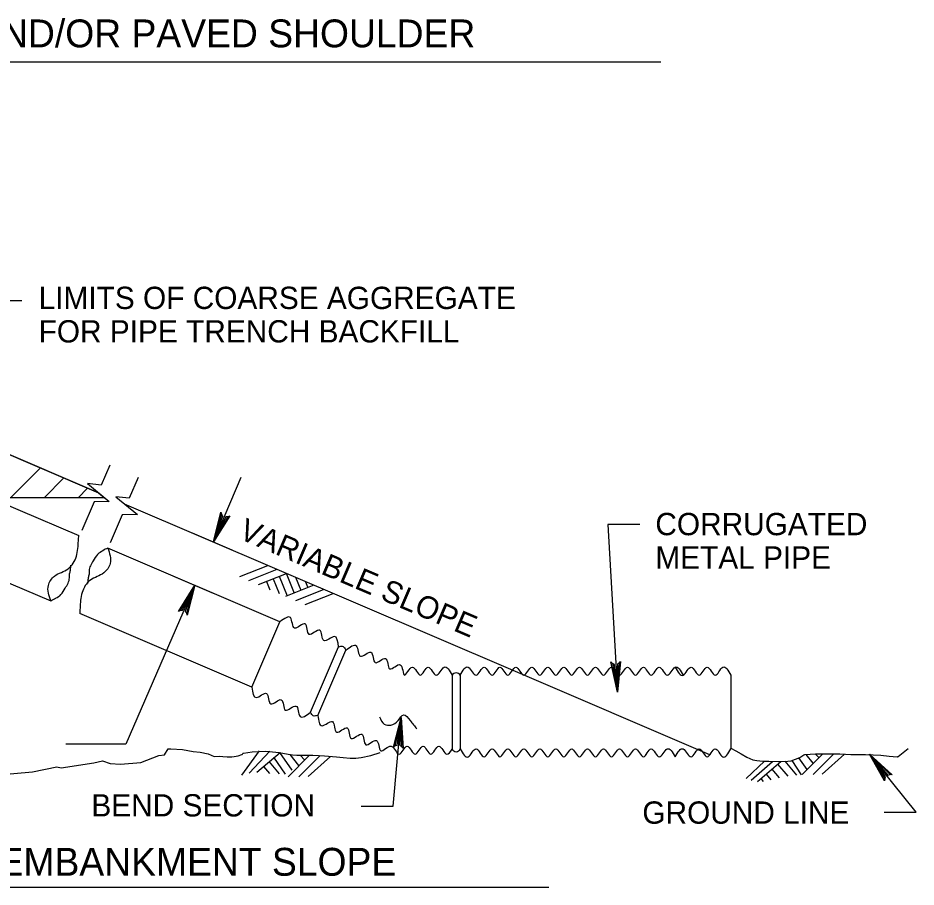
# Model space of a CAD drawing. Extents: x 637898 to 638802, y 298167 to 298761.
# Drawn here: x 638068.2 to 638203.5, y 298468.9 to 298599.9 of the extents above; entities that cross this region are included whole.
import ezdxf

# ---------------------------------------------------------------- set-up
doc = ezdxf.new("R2010")
doc.units = 0
doc.layers.add('2', color=7, linetype='Continuous')
doc.layers.add('3', color=7, linetype='Continuous')

msp = doc.modelspace()

# ---------------------------------------------------------------- linework, layer by layer
at = {"layer": '2'}
for p, q in [((638080.36, 298528.3), (638029.92, 298549.91)), ((638051.41, 298532.97), (638077.37, 298521.84)), ((638082.04, 298532.44), (638080.75, 298529.45)), ((638086.3, 298530.58), (638084.97, 298527.46)), ((638101.81, 298530.6), (638097.65, 298520.88)), ((638081.26, 298527.55), (637966.76, 298527.55)), ((638079.68, 298526.95), (638077.82, 298522.59)), ((638083.89, 298524.95), (638082.08, 298520.73)), ((638047.19, 298523.12), (638073.15, 298512)), ((638094.44, 298522.26), (638100.41, 298519.7)), ((638107.69, 298508.85), (638081.74, 298519.97)), ((638101.63, 298515.66), (638105.85, 298517.35)), ((638103.01, 298515.07), (638107.26, 298516.77)), ((638104.44, 298514.46), (638108.69, 298516.15)), ((638108.62, 298516.18), (638109.82, 298513.19)), ((638091.64, 298515.73), (638097.61, 298513.17)), ((638105.65, 298514.94), (638106.15, 298513.67)), ((638106.67, 298515.35), (638107.56, 298513.12)), ((638107.57, 298515.71), (638108.75, 298512.78)), ((638110.05, 298515.57), (638110.83, 298513.62)), ((638111.5, 298514.95), (638111.87, 298514.02)), ((638108.56, 298512.69), (638112.82, 298514.4)), ((638110.07, 298512.05), (638114.26, 298513.73)), ((638111.5, 298511.44), (638115.69, 298513.11)), ((638103.47, 298499), (638077.52, 298510.12)), ((638103.47, 298499), (638107.69, 298508.85)), ((638112.29, 298495.22), (638116.51, 298505.07)), ((638113.4, 298494.75), (638117.62, 298504.59)), ((638117.62, 298504.59), (638117.62, 298504.59)), ((638119.82, 298503.65), (638119.82, 298503.65)), ((638122.03, 298502.7), (638122.03, 298502.7)), ((638124.23, 298501.76), (638124.23, 298501.76)), ((638142.75, 298501.56), (638172.39, 298488.85)), ((638126.44, 298500.81), (638126.44, 298500.81)), ((638128.84, 298500.81), (638128.84, 298500.81)), ((638131.24, 298500.81), (638131.24, 298500.81)), ((638133.64, 298500.81), (638133.64, 298500.81)), ((638133.64, 298500.81), (638133.64, 298489.7)), ((638134.84, 298500.81), (638134.84, 298489.7)), ((638134.84, 298500.81), (638134.84, 298500.81)), ((638137.24, 298500.81), (638137.24, 298500.81)), ((638139.64, 298500.81), (638139.64, 298500.81)), ((638142.04, 298500.81), (638142.04, 298500.81)), ((638144.44, 298500.81), (638144.44, 298500.81)), ((638146.84, 298500.81), (638146.84, 298500.81)), ((638149.24, 298500.81), (638149.24, 298500.81)), ((638151.64, 298500.81), (638151.64, 298500.81)), ((638154.04, 298500.81), (638154.04, 298500.81)), ((638156.44, 298500.81), (638156.44, 298500.81)), ((638158.84, 298500.81), (638158.84, 298500.81)), ((638161.24, 298500.81), (638161.24, 298500.81)), ((638163.64, 298500.81), (638163.64, 298500.81)), ((638166.04, 298500.81), (638166.04, 298500.81)), ((638168.44, 298500.81), (638168.44, 298500.81)), ((638168.44, 298500.81), (638168.44, 298500.81)), ((638170.84, 298500.81), (638170.84, 298500.81)), ((638173.24, 298500.81), (638173.24, 298500.81)), ((638175.64, 298500.81), (638175.64, 298500.81)), ((638175.64, 298500.81), (638175.64, 298489.7)), ((638113.4, 298494.75), (638113.4, 298494.75)), ((638115.6, 298493.8), (638115.6, 298493.8)), ((638117.81, 298492.86), (638117.81, 298492.86)), ((638120.01, 298491.91), (638120.01, 298491.91)), ((638122.22, 298490.96), (638122.22, 298490.96)), ((638124.44, 298490.1), (638124.44, 298490.1)), ((638126.84, 298490.1), (638126.84, 298490.1)), ((638129.24, 298490.1), (638129.24, 298490.1)), ((638131.64, 298490.1), (638131.64, 298490.1)), ((638101.93, 298485.75), (638104.62, 298489.42)), ((638103.03, 298486.02), (638106.15, 298489.35)), ((638104.22, 298486.2), (638107.7, 298489.16)), ((638107.63, 298489.16), (638109.45, 298486.49)), ((638108.91, 298485.49), (638112.15, 298488.75)), ((638109.15, 298488.84), (638110.48, 298487.21)), ((638110.72, 298488.73), (638111.43, 298488.02)), ((638134.84, 298489.7), (638134.84, 298489.7)), ((638137.24, 298489.7), (638137.24, 298489.7)), ((638139.64, 298489.7), (638139.64, 298489.7)), ((638142.04, 298489.7), (638142.04, 298489.7)), ((638144.44, 298489.7), (638144.44, 298489.7)), ((638146.84, 298489.7), (638146.84, 298489.7)), ((638149.24, 298489.7), (638149.24, 298489.7)), ((638151.64, 298489.7), (638151.64, 298489.7)), ((638154.04, 298489.7), (638154.04, 298489.7)), ((638156.44, 298489.7), (638156.44, 298489.7)), ((638158.84, 298489.7), (638158.84, 298489.7)), ((638161.24, 298489.7), (638161.24, 298489.7)), ((638163.64, 298489.7), (638163.64, 298489.7)), ((638166.04, 298489.7), (638166.04, 298489.7)), ((638168.44, 298489.7), (638168.44, 298489.7)), ((638168.44, 298489.7), (638168.44, 298489.7)), ((638170.84, 298489.7), (638170.84, 298489.7)), ((638173.24, 298489.7), (638173.24, 298489.7)), ((638175.64, 298489.7), (638175.64, 298489.7)), ((638186.39, 298485.85), (638189.47, 298488.94)), ((638186.91, 298488.85), (638187.96, 298487.56)), ((638188.02, 298485.85), (638191.13, 298488.95)), ((638188.35, 298488.93), (638188.91, 298488.37)), ((638189.4, 298485.88), (638192.77, 298488.9)), ((638106.04, 298487.75), (638107.59, 298485.93)), ((638106.71, 298488.47), (638108.48, 298485.87)), ((638110.54, 298485.5), (638113.74, 298488.69)), ((638111.92, 298485.53), (638115.29, 298488.54)), ((638177.94, 298485.21), (638180.7, 298487.85)), ((638178.7, 298484.96), (638181.88, 298487.82)), ((638179.62, 298484.8), (638183.17, 298487.81)), ((638182.68, 298487.39), (638184.22, 298485.58)), ((638183.75, 298487.83), (638185.53, 298485.74)), ((638184.79, 298487.94), (638186.24, 298485.8)), ((638187.11, 298486.57), (638185.89, 298488.35)), ((638105.2, 298487.04), (638106.09, 298486)), ((638181.79, 298486.63), (638182.91, 298485.31)), ((638180.12, 298485.22), (638180.5, 298484.76)), ((638180.93, 298485.91), (638181.66, 298485.04)), ((638006.78, 298468.88), (638148.19, 298468.88))]:
    msp.add_line(p, q, dxfattribs=at)
for points in [[(638068.8, 298557.21), (638064, 298557.21), (638048.7, 298538.9)], [(638067.08, 298527.55), (638071.58, 298532.06)], [(638072.17, 298527.55), (638075.14, 298530.53)], [(638080.75, 298529.45), (638078.68, 298529.67), (638081.95, 298526.99), (638079.68, 298526.95)], [(638077.26, 298527.55), (638078.71, 298529)], [(638084.97, 298527.46), (638082.94, 298527.67), (638086.21, 298525), (638083.89, 298524.95)], [(638084.19, 298526.65), (638142.75, 298501.56)], [(638099.86, 298524.68), (638099.51, 298524.65), (638097.65, 298520.88), (638099.86, 298524.68), (638100.12, 298524.81), (638097.65, 298520.88), (638099.1, 298524.82), (638098.88, 298525.09), (638097.65, 298520.88), (638098.78, 298525.39), (638098.88, 298525.09)], [(638161.89, 298523.5), (638157.09, 298523.5), (638158.54, 298498.27)], [(638094.85, 298514.35), (638084.44, 298490.39), (638075.44, 298490.39)], [(638092.64, 298510.55), (638092.99, 298510.58), (638094.85, 298514.35), (638092.64, 298510.55), (638092.38, 298510.42), (638094.85, 298514.35), (638093.4, 298510.41), (638093.63, 298510.15), (638094.85, 298514.35), (638093.72, 298509.85), (638093.63, 298510.15)], [(638158.84, 298502.65), (638158.53, 298502.47), (638158.54, 298498.27), (638158.84, 298502.65), (638159.02, 298502.89), (638158.54, 298498.27), (638158.1, 298502.44), (638157.78, 298502.58), (638158.54, 298498.27), (638157.55, 298502.8), (638157.78, 298502.58)], [(638119.92, 298481.08), (638124.72, 298481.08), (638125.95, 298494.44)], [(638125.01, 298490.15), (638125.34, 298490.28), (638125.95, 298494.44), (638125.01, 298490.15), (638124.8, 298489.94), (638125.95, 298494.44), (638125.77, 298490.24), (638126.07, 298490.06), (638125.95, 298494.44), (638126.26, 298489.81), (638126.07, 298490.06)], [(638060.82, 298485.41), (638070.42, 298486.24), (638074.06, 298487.01), (638074.7, 298486.82), (638079.63, 298487.58), (638080.97, 298487.9), (638082.12, 298487.52), (638083.65, 298487.39), (638086.72, 298487.65), (638089.45, 298488.71), (638090.28, 298488.79), (638090.82, 298489.7), (638091.23, 298489.69), (638092.99, 298489.63), (638094.59, 298489.31), (638095.68, 298489.18), (638096.89, 298488.93), (638097.79, 298488.54), (638098.64, 298488.62), (638099.08, 298488.54), (638099.74, 298488.5), (638100.41, 298488.51), (638100.8, 298488.54), (638101.38, 298488.65), (638101.95, 298488.84), (638101.98, 298488.86), (638102.03, 298488.91), (638102.09, 298489), (638102.13, 298489.04), (638102.17, 298489.06), (638103.52, 298489.27), (638105.55, 298489.33), (638107.58, 298489.17), (638108.9, 298488.92), (638109.56, 298488.8), (638110.22, 298488.73), (638111.44, 298488.73), (638112.65, 298488.73), (638114.42, 298488.63), (638116.18, 298488.51), (638117.23, 298488.4), (638118.27, 298488.29), (638119.1, 298488.29), (638119.93, 298488.4), (638121.38, 298488.71), (638122.8, 298489.17)], [(638175.63, 298489.83), (638176.4, 298489.38), (638177.18, 298488.95), (638178.03, 298488.47), (638178.47, 298488.25), (638178.94, 298488.07), (638179.54, 298487.93), (638180.45, 298487.86), (638181.37, 298487.85), (638182.8, 298487.8), (638184.23, 298487.85), (638184.69, 298487.92), (638185.35, 298488.14), (638186, 298488.4), (638186.19, 298488.51), (638186.47, 298488.71), (638186.61, 298488.8), (638186.77, 298488.84), (638188.37, 298488.93), (638189.97, 298488.95), (638191.02, 298488.96), (638192.07, 298488.95), (638192.89, 298488.89), (638193.72, 298488.84), (638194.82, 298488.84), (638195.93, 298488.84), (638197.08, 298488.79), (638198.24, 298488.73), (638199.46, 298488.61), (638200.67, 298488.51), (638200.73, 298488.52), (638200.77, 298488.53), (638200.83, 298488.57), (638202.35, 298489.76)], [(638198.73, 298480.18), (638203.53, 298480.18), (638196.5, 298488.89)], [(638198.81, 298485.16), (638198.95, 298485.48), (638196.5, 298488.89), (638198.81, 298485.16), (638198.8, 298484.86), (638196.5, 298488.89), (638199.29, 298485.76), (638199.63, 298485.84), (638196.5, 298488.89), (638199.94, 298485.78), (638199.63, 298485.84)]]:
    msp.add_lwpolyline(points, dxfattribs=at)
msp.add_lwpolyline([(637968.89, 298539.81), (637966.76, 298541.57), (637966.76, 298545.87), (638039.35, 298545.87), (638080.36, 298528.3), (638081.26, 298527.55), (637966.76, 298527.55), (637966.76, 298537.23), (637964.95, 298538.94)], close=True, dxfattribs=at)
for centre, radius, start, end in [((638134.24, 298500.46), 0.698, 30.7717, 149.2283), ((638134.24, 298489.9), 0.633, 198.7071, 341.2929)]:
    msp.add_arc(centre, radius, start, end, dxfattribs=at)
for points in [[(638073.15, 298512), (638072.79, 298514.34), (638073.73, 298515.75), (638075.76, 298516.84), (638077.01, 298518.72), (638077.32, 298521.06), (638077.37, 298521.84)], [(638081.74, 298519.97), (638082.09, 298517.63), (638081.15, 298516.22), (638079.12, 298515.13), (638077.87, 298513.25), (638077.56, 298510.91), (638077.52, 298510.12)], [(638081.74, 298519.97), (638081, 298519.57), (638080.21, 298519.01), (638079.55, 298518.06), (638079.12, 298517.3), (638078.92, 298516.51), (638078.92, 298516.01), (638078.79, 298515.49), (638078.73, 298514.86), (638078.69, 298514.6)], [(638073.15, 298512), (638073.88, 298512.39), (638074.67, 298512.95), (638075.33, 298513.91), (638075.76, 298514.67), (638075.96, 298515.46), (638075.96, 298515.95), (638076.09, 298516.48), (638076.16, 298517.11), (638076.19, 298517.37)], [(638116.51, 298505.07), (638115.88, 298506.64), (638114.31, 298506.01), (638113.68, 298507.59), (638112.1, 298506.96), (638111.47, 298508.53), (638109.9, 298507.9), (638109.27, 298509.48), (638107.69, 298508.85)], [(638116.51, 298505.07), (638117.2, 298505.13), (638117.62, 298504.59)], [(638117.62, 298504.59), (638119.19, 298505.23), (638119.82, 298503.65), (638121.4, 298504.28), (638122.03, 298502.7), (638123.6, 298503.33), (638124.23, 298501.76), (638125.81, 298502.39), (638126.44, 298500.81), (638127.64, 298502.01), (638128.84, 298500.81), (638130.04, 298502.01), (638131.24, 298500.81), (638132.44, 298502.01), (638133.64, 298500.81)], [(638134.84, 298500.81), (638136.04, 298502.01), (638137.24, 298500.81), (638138.44, 298502.01), (638139.64, 298500.81), (638140.84, 298502.01), (638142.04, 298500.81), (638143.24, 298502.01), (638144.44, 298500.81), (638145.64, 298502.01), (638146.84, 298500.81), (638148.04, 298502.01), (638149.24, 298500.81), (638150.44, 298502.01), (638151.64, 298500.81), (638152.84, 298502.01), (638154.04, 298500.81), (638155.24, 298502.01), (638156.44, 298500.81), (638157.64, 298502.01), (638158.84, 298500.81), (638160.04, 298502.01), (638161.24, 298500.81), (638162.44, 298502.01), (638163.64, 298500.81), (638164.84, 298502.01), (638166.04, 298500.81), (638167.24, 298502.01), (638168.44, 298500.81)], [(638167.24, 298502.01), (638168.44, 298500.81), (638169.64, 298502.01), (638170.84, 298500.81), (638172.04, 298502.01), (638173.24, 298500.81), (638174.44, 298502.01), (638175.64, 298500.81)], [(638103.47, 298499), (638104.1, 298497.43), (638105.67, 298498.06), (638106.3, 298496.48), (638107.88, 298497.11), (638108.51, 298495.53), (638110.09, 298496.16), (638110.72, 298494.59), (638112.29, 298495.22)], [(638113.4, 298494.75), (638112.71, 298494.68), (638112.29, 298495.22)], [(638113.4, 298494.75), (638114.03, 298493.17), (638115.6, 298493.8), (638116.23, 298492.22), (638117.81, 298492.86), (638118.44, 298491.28), (638120.01, 298491.91), (638120.64, 298490.33), (638122.22, 298490.96), (638122.9, 298489.42), (638124.44, 298490.1), (638125.64, 298488.9), (638126.84, 298490.1), (638128.04, 298488.9), (638129.24, 298490.1), (638130.44, 298488.9), (638131.64, 298490.1), (638132.84, 298488.9), (638133.62, 298489.68)], [(638122.7, 298494.54), (638123.4, 298493.42), (638124.38, 298493.28), (638125.5, 298493.98), (638126.33, 298494.82), (638127.31, 298493.98), (638128.29, 298492.72)], [(638134.84, 298489.7), (638136.04, 298488.5), (638137.24, 298489.7), (638138.44, 298488.5), (638139.64, 298489.7), (638140.84, 298488.5), (638142.04, 298489.7), (638143.24, 298488.5), (638144.44, 298489.7), (638145.64, 298488.5), (638146.84, 298489.7), (638148.04, 298488.5), (638149.24, 298489.7), (638150.44, 298488.5), (638151.64, 298489.7), (638152.84, 298488.5), (638154.04, 298489.7), (638155.24, 298488.5), (638156.44, 298489.7), (638157.64, 298488.5), (638158.84, 298489.7), (638160.04, 298488.5), (638161.24, 298489.7), (638162.44, 298488.5), (638163.64, 298489.7), (638164.84, 298488.5), (638166.04, 298489.7), (638167.24, 298488.5)], [(638167.24, 298488.5), (638168.44, 298489.7), (638169.64, 298488.5), (638170.84, 298489.7), (638172.04, 298488.5), (638173.24, 298489.7), (638174.44, 298488.5), (638175.64, 298489.7)]]:
    msp.add_spline(points, degree=3, dxfattribs=at)
at = {"layer": '3'}
msp.add_line((637983.65, 298593.22), (638165.1, 298593.22), dxfattribs=at)

# ---------------------------------------------------------------- texts
at = {"layer": '2'}
msp.add_text('OUTLET PIPE THRU EMBANKMENT SLOPE', height=4.2, dxfattribs=at).set_placement((638010.05, 298470.58))
at = {"layer": '3'}
for s, height, p in [('ADJACENT TO STRUCTURE AND/OR PAVED SHOULDER', 4.2, (637985.15, 298595.43)), ('LIMITS OF COARSE AGGREGATE', 3.36, (638071.32, 298555.99)), ('FOR PIPE TRENCH BACKFILL', 3.36, (638071.32, 298550.95)), ('CORRUGATED', 3.36, (638164.25, 298521.9)), ('METAL PIPE', 3.36, (638164.25, 298516.86)), ('BEND SECTION', 3.36, (638079.27, 298479.51)), ('GROUND LINE', 3.36, (638162.29, 298478.42))]:
    msp.add_text(s, height=height, dxfattribs=at).set_placement(p)
msp.add_text('VARIABLE SLOPE', height=3.36, rotation=336.8014, dxfattribs=at).set_placement((638101.3, 298521.46))

doc.saveas('drawing.dxf')
